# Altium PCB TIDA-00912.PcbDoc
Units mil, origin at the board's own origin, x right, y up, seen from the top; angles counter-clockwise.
Board outline 2371.35 x 1639 mil, 4 copper layers (Top Layer, GND, PWR, Bottom Layer), stack 79.834 mil thick; 79 components, 34 nets, 162 pads, 39 vias.
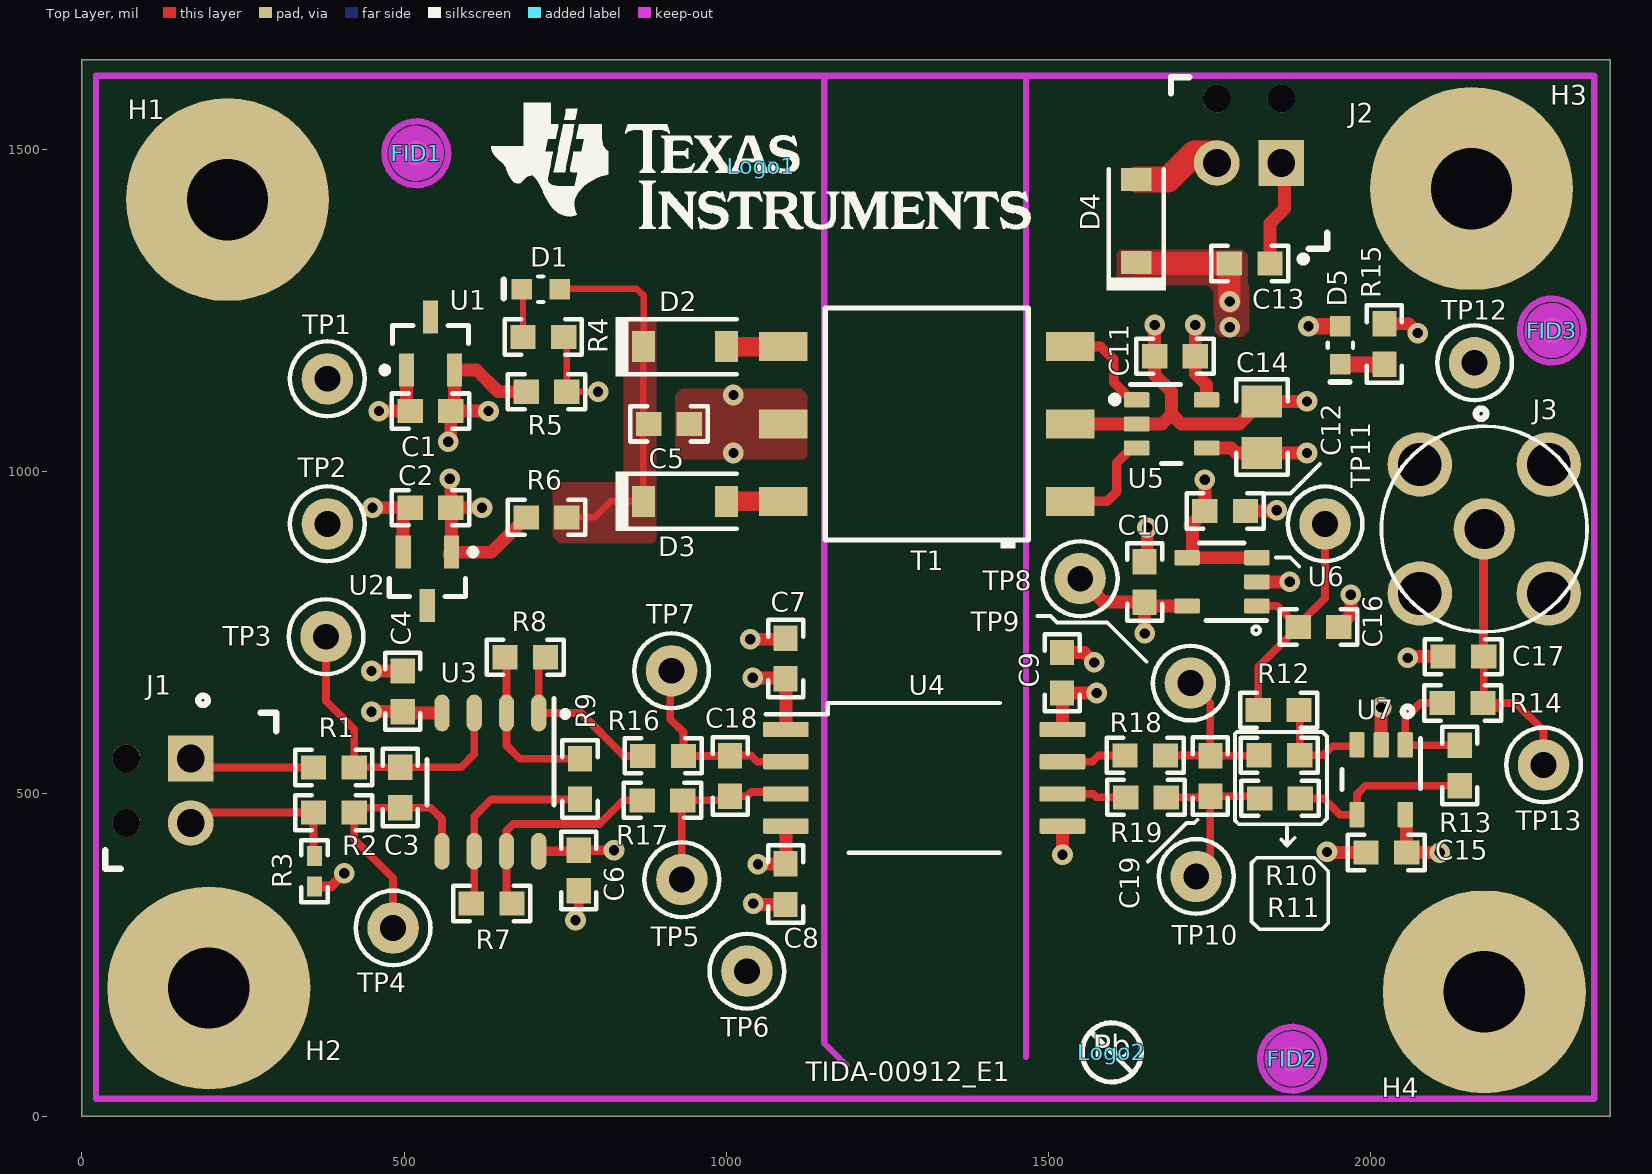
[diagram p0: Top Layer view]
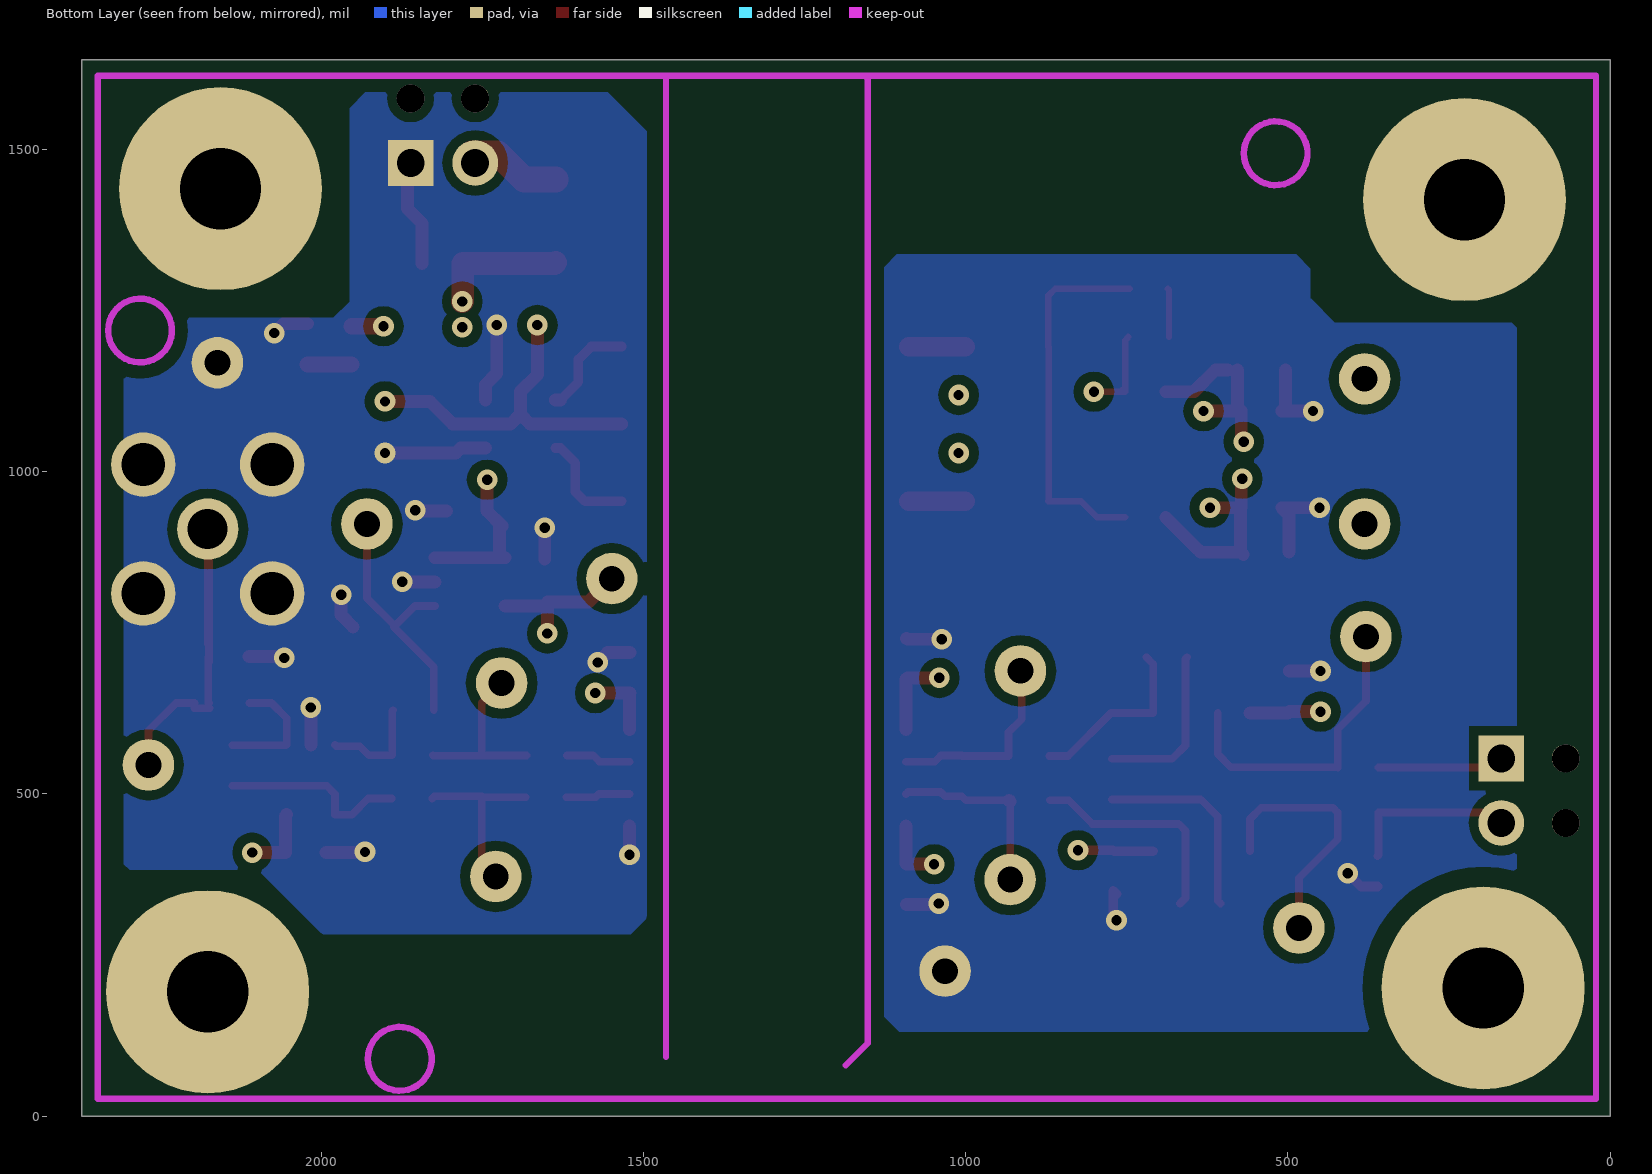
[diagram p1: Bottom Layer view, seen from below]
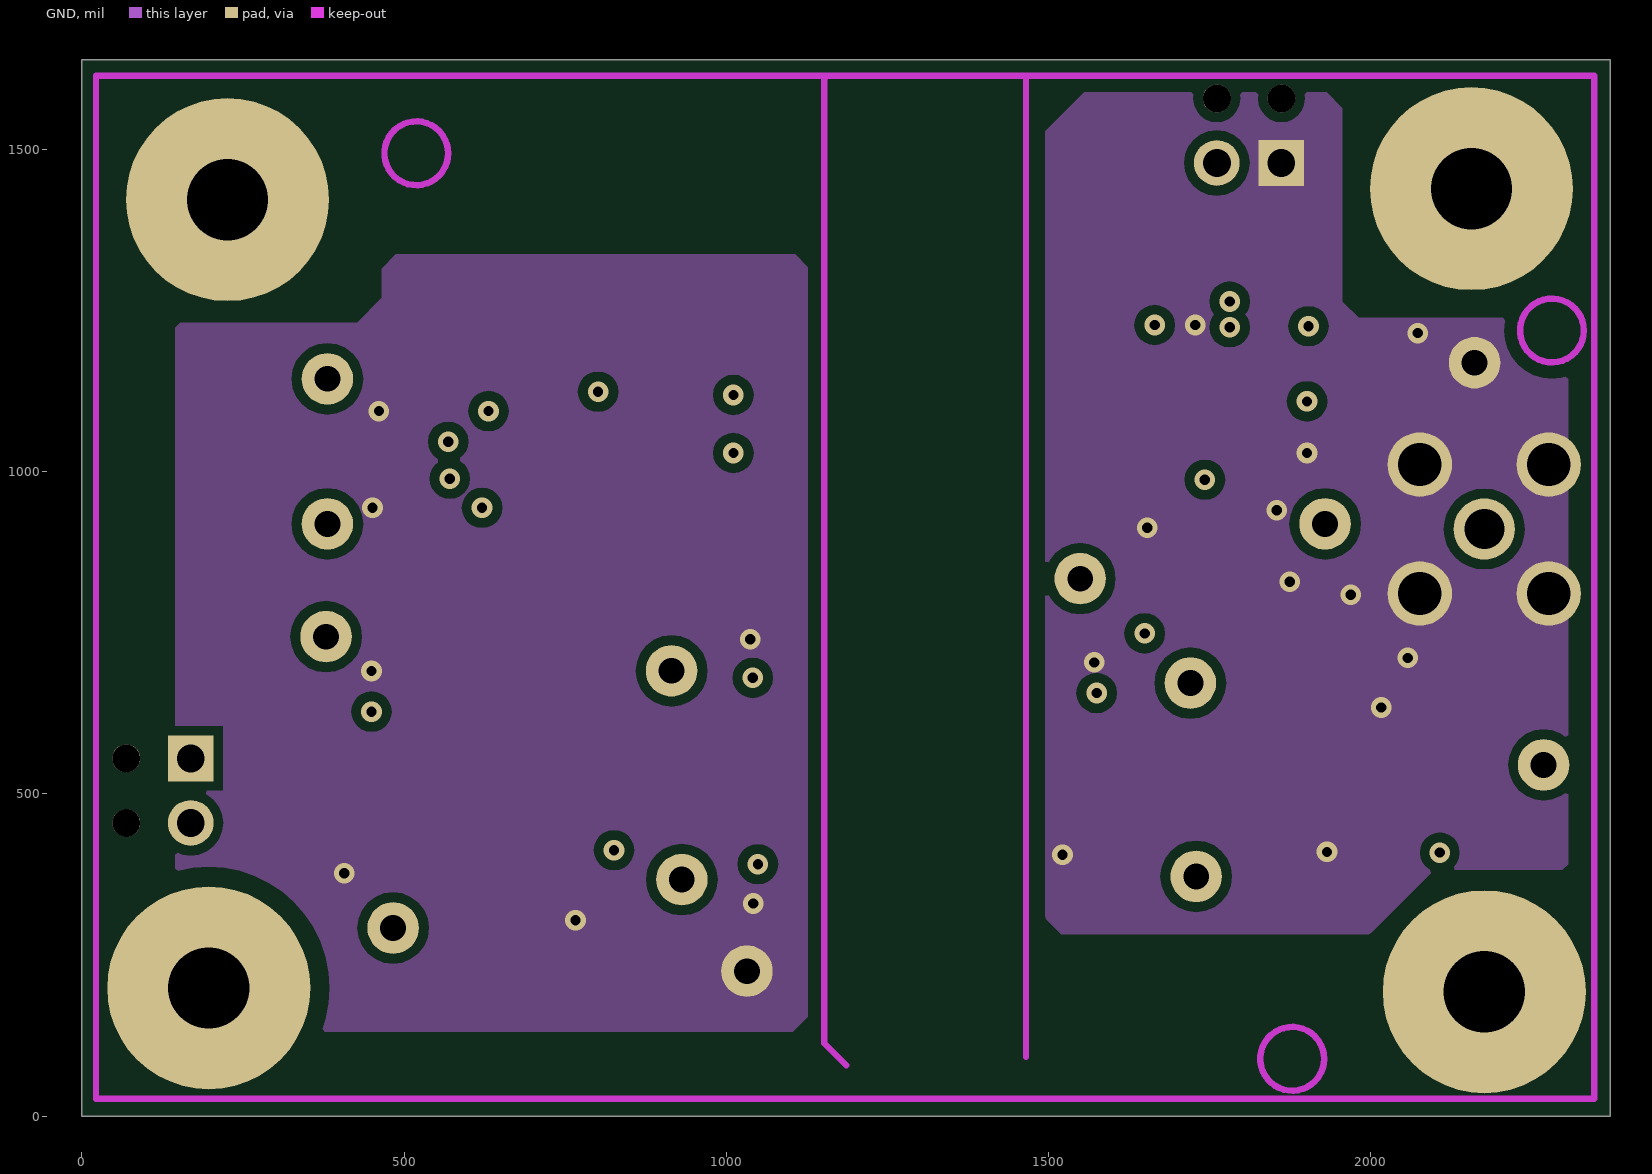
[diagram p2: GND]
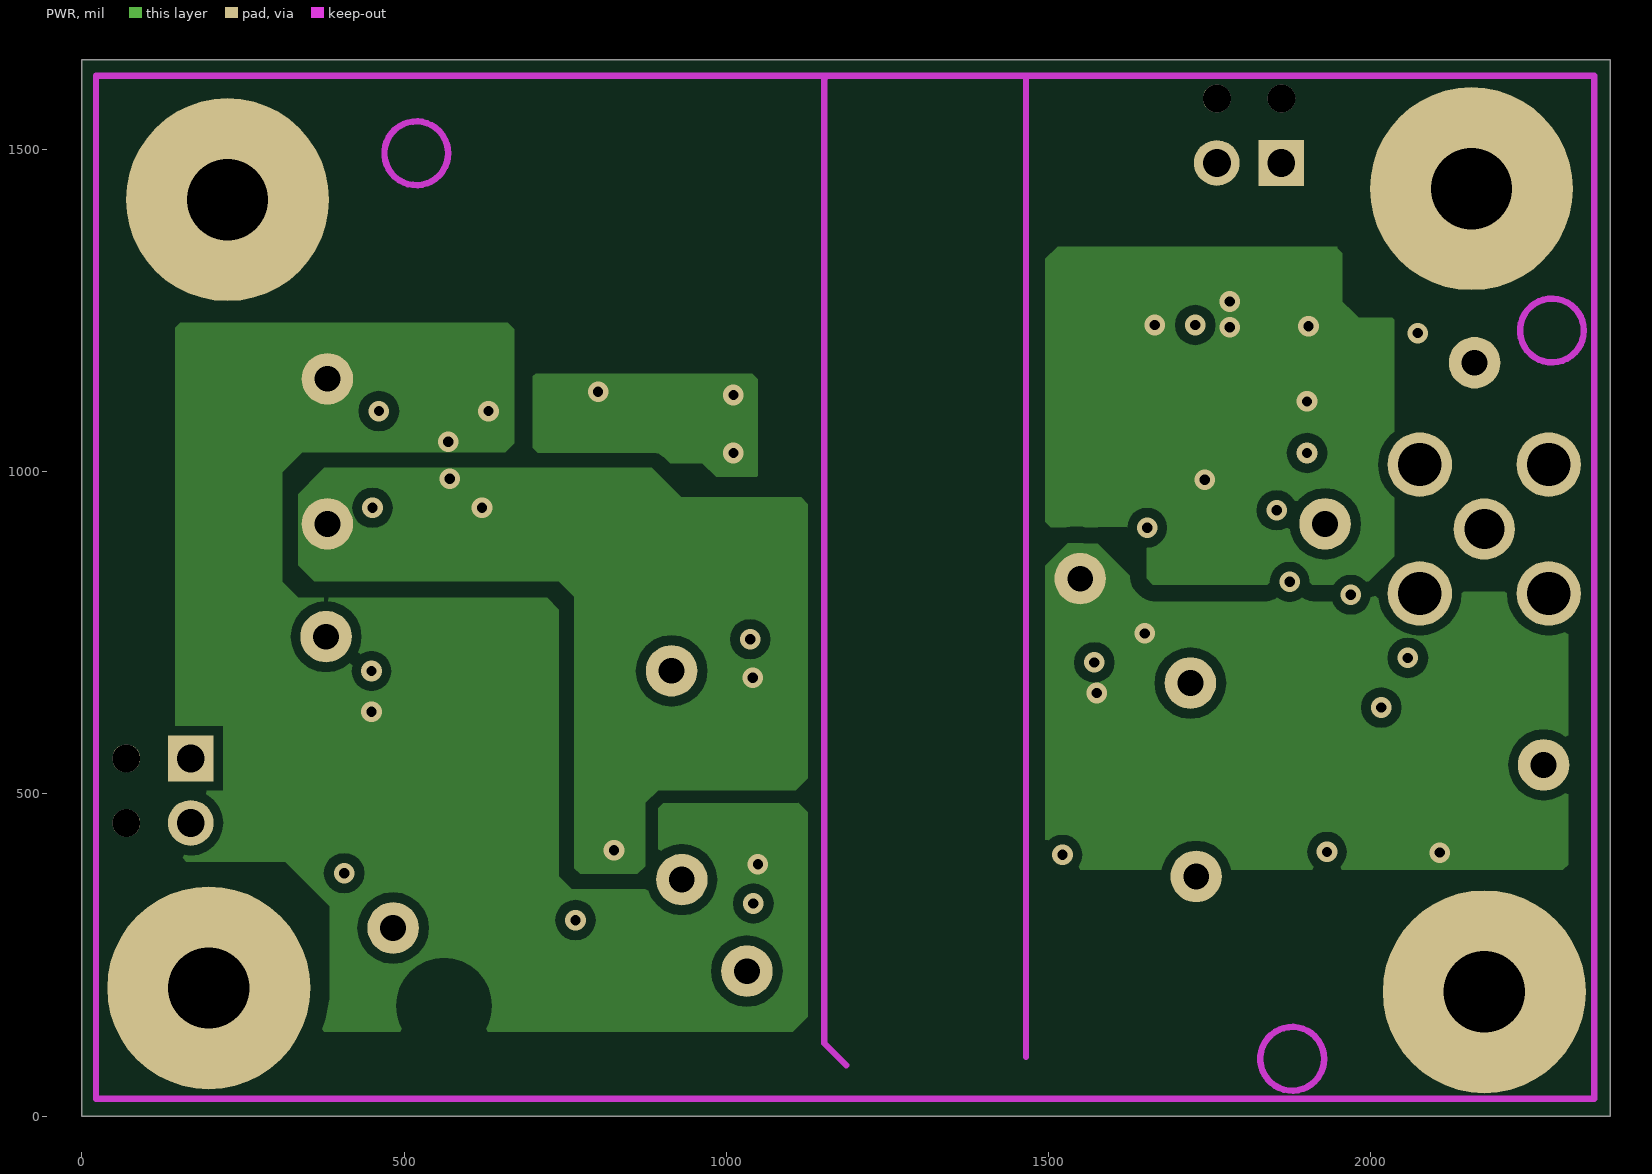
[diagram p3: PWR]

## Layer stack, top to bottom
Top Solder: solder mask 0.4, Solder Resist, Dk 3.5
Top Layer: signal copper 1.4
Dielectric1: core 59.2, FR-4, Dk 4.8
GND: signal copper 1.417
Dielectric 2: prepreg 5, Dk 4.2
PWR: signal copper 1.417
Dielectric 3: core 10, Dk 4.2
Bottom Layer: signal copper 1.4
Bottom Solder: solder mask 0.4, Solder Resist, Dk 3.5

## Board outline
0,0 0,1639 2371.36,1639 2371.36,0

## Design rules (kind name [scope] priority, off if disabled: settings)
AcuteAngle [All] p1: minimum=4.50000000000000E+0001 checktracksonly=FALSE
AssemblyTestPointUsage [All] p1: valid=2
Clearance Clearance_MTG_COPPER [InPadClass('MTG') vs InPolygon] p1: gap=30
Clearance Clearance_Boardedge_poly [OnCopper and InPolygon vs IsKeepOut] p2: gap=20
Clearance "Shape to Shape" [InPolygon vs InPolygon] p3: gap=20
Clearance "shape to all" [InPolygon] p4: gap=15
Clearance Clearance_u1 [IsPad vs IsPad] p5: gap=7.87
Clearance "Clearance_via_thr pin" [IsVia vs IsThruPin] p6: gap=8
Clearance "SMD to Via" [IsSMTPin vs IsVia] p7: gap=8
Clearance [All] p8: gap=8
DiffPairsRouting DiffPair_DiffPairsRouting [InDifferentialPair ('kan')] p1: maxlimit=10 minlimit=10 mostfreqgap=10 toplayer_minwidth=15 toplayer_maxwidth=15 toplayer_prefwidth=15 midlayer1_minwidth=15 midlayer1_maxwidth=15 midlayer1_prefwidth=15 midlayer2_minwidth=15 midlayer2_maxwidth=15 midlayer2_prefwidth=15 bottomlayer_minwidth=15 bottomlayer_maxwidth=15 bottomlayer_prefwidth=15 maxuncoupledlength=500
DiffPairsRouting DiffPair_DiffPairsRouting_1 [InDifferentialPair ('kan')] p2: maxlimit=10 minlimit=10 mostfreqgap=10 toplayer_minwidth=15 toplayer_maxwidth=15 toplayer_prefwidth=15 midlayer1_minwidth=15 midlayer1_maxwidth=15 midlayer1_prefwidth=15 midlayer2_minwidth=15 midlayer2_maxwidth=15 midlayer2_prefwidth=15 bottomlayer_minwidth=15 bottomlayer_maxwidth=15 bottomlayer_prefwidth=15 maxuncoupledlength=500
DiffPairsRouting [All] p3: maxlimit=100 minlimit=10 mostfreqgap=10 toplayer_minwidth=15 toplayer_maxwidth=15 toplayer_prefwidth=15 midlayer1_minwidth=15 midlayer1_maxwidth=15 midlayer1_prefwidth=15 midlayer2_minwidth=15 midlayer2_maxwidth=15 midlayer2_prefwidth=15 bottomlayer_minwidth=15 bottomlayer_maxwidth=15 bottomlayer_prefwidth=15 maxuncoupledlength=1000
FabricationTestPointUsage TestPointUsage [All] p1: valid=2 allowmultiple=FALSE
FabricationTestpoint Testpoint [All] p1: side=3 testpointundercomponent=TRUE minsize=40 maxsize=100 preferedsize=60 minholesize=0 maxholesize=40 preferedholesize=32 testpointgrid=1 allowsidetop=TRUE allowsidebottom=TRUE usegrid=TRUE gridtolerance=0.01
FanoutControl Fanout_LCC [IsLCC] p1: bgadir=Out bgaviamode=Centered fanoutstyle=Auto fanoutdirection=Alternating viagrid=1 // Fanout_LCC (Default Rule)
FanoutControl Fanout_BGA [IsBGA] p2: bgadir=Out bgaviamode=Centered fanoutstyle=Auto fanoutdirection=Alternating viagrid=1 // Fanout_BGA (Default Rule)
FanoutControl Fanout_Default [All] p4: bgadir=Out bgaviamode=Centered fanoutstyle=Auto fanoutdirection=Alternating viagrid=1 // Fanout_Default (Default Rule)
FanoutControl Fanout_Small [(CompPinCount < 5)] p5: bgadir=Out bgaviamode=Centered fanoutstyle=Auto fanoutdirection=OutThenIn viagrid=1 // Fanout_Small (Default Rule)
HoleSize [All] p1: absolutevalues=TRUE maxlimit=251 minlimit=7 maxpercent=80.000 minpercent=20.000
MatchedLengths DiffPair_MatchedLengths [InDifferentialPair ('kan')] p1: tolerance=1000 checknetsindiffpair=TRUE checkdiffpairvsdiffpair=TRUE checkothers=TRUE
MatchedLengths DiffPair_MatchedLengths_1 [InDifferentialPair ('kan')] p2: tolerance=1000 checknetsindiffpair=TRUE checkdiffpairvsdiffpair=TRUE checkothers=TRUE
MinimumAnnularRing [All] p1: minimumring=5
MinimumAnnularRing MinimumAnnularRing_ThermalPadVias [IsVia and InAnyComponent] p2: minimumring=5.91
MinimumSolderMaskSliver MinimumSolderMaskSliver_Logo [InComponentClass('Logo') vs InComponentClass('Logo')] p1: minsoldermaskwidth=0.7
MinimumSolderMaskSliver [All] p2: minsoldermaskwidth=3.94
PlaneClearance [All] p1: clearance=15
PlaneConnect [All] p1: planeconnectstyle=Direct reliefexpansion=10 reliefentries=4 reliefconductorwidth=10 reliefairgap=10
PolygonConnect [All] p1: connectstyle=Direct reliefconductorwidth=10 reliefentries=4 polygonreliefangle="90 Angle" airgapwidth=10
RoutingVias RoutingVias_power [InNetClass('POWER')] p1: holewidth=16 width=32 viastyle="Through Hole" minholewidth=7.87 minwidth=19.68 maxholewidth=16 maxwidth=32
RoutingVias ThermalPadVias [IsVia and InAnyComponent] p2: holewidth=8 width=20 viastyle="Through Hole" minholewidth=7.87 minwidth=19 maxholewidth=12 maxwidth=24
RoutingVias [All] p3: holewidth=12 width=24 viastyle="Through Hole" minholewidth=12 minwidth=24 maxholewidth=16 maxwidth=32
SMDToCorner [All] p1: distance=30000
SilkToSilkClearance [All] p1: silktosilkclearance=5
SilkToSolderMaskClearance SilkscreenOverComponentPads [IsPad] p1: minsilkscreentomaskgap=5 clearancetoexposedcopper=TRUE
SolderMaskExpansion [All] p1: expansion=3
UnpouredPolygon [All] p1: allowunpoured=FALSE
Width Width_power [InNetClass('pwr')] p1: maxlimit=200 minlimit=8 preferedwidth=20
Width [All] p2: maxlimit=100 minlimit=10 preferedwidth=20 checkconnectedcopper=TRUE
15 further rules are at their usual default settings.

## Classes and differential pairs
pad class MTG: H1-1 H2-1 H3-1
component class TIDA_00912_Schematic: C1 C2 C3 C4 C5 C6 C7 C8 C9 C10 C11 C12 C13 C14 C15 C16 C17 C18 C19 D1 D2 D3 D4 D5 J1 J2 J3 R1 R2 R3 R4 R5 R6 R7 R8 R9 R10 R11 R12 R13 R14 R15 R16 R17 R18 R19 T1 TP1 TP2 TP3 TP4 TP5 TP6 TP7 TP8 TP9 TP10 TP11 TP12 TP13 U1 U2 U3 U4 U5 U6 U7
component class AssemblyNote: ZZ1 ZZ2 ZZ3
component class FiducialMark: FID1 FID2 FID3
component class Logo: Logo1
component class "Mounting Holes": H1 H2 H3 H4
component class TIDA_00912_TID_Hardware: !PCB FID1 FID2 FID3 H1 H2 H3 H4 Logo1 Logo2 ZZ1 ZZ2 ZZ3

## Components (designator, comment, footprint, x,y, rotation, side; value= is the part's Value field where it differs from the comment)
C1 "C1608X7R1E105K080AB" 0603 541,1094 r0 top (schematic designator C21)
C2 "C1608X7R1E105K080AB" 0603 541,944 r180 top (schematic designator C22)
C3 "GRM188R71E224KA88D" 0603 494,510 r270 top (schematic designator C17)
C4 "C0603C104J3RAC" 0603 498,659.2 r270 top (schematic designator C9)
C5 "GRM188R6YA106MA73" 0603 911,1074 r0 top (schematic designator C20)
C6 "C0603C104J3RAC" 0603 771,381.2 r270 top
C7 "C0603C104J3RAC" 0603 1092,710 r90 top
C8 "C0603C104J3RAC" 0603 1092,360 r270 top (schematic designator C12)
C9 "C0603C104J3RAC" 0603 1521,688 r270 top (schematic designator C8)
C10 "C0603C104J3RAC" 0603 1649,829 r90 top (schematic designator C14)
C11 "C0603C104J3RAC" 0603 1696,1179 r0 top (schematic designator C1)
C12 "C0603C104J3RAC" 0603 1774,939 r180 top (schematic designator C2)
C13 "C1608X5R1E106M080AC" 0603 1812,1323 r0 top (schematic designator C3)
C14 "C2012X5R1E106K125AB" 0805_HV 1831,1069 r270 top (schematic designator C4)
C15 "C0603C104J3RAC" 0603 2024,409 r0 top (schematic designator C10)
C16 "C0603C104J3RAC" 0603 1919,759 r0 top (schematic designator C15)
C17 "C0603C224J3RAC7867" 0603 2143.5,713 r180 top (schematic designator C19)
C18 "C1608C0G1H331J" 0603 1006,528 r270 top
C19 "C1608C0G1H331J" 0603 1751,527.7 r270 top
D1 "LG L29K-G2J1-24-Z" "LG L29K_GREEN" 712,1283 r180 top (schematic designator D5)
D2 "MBR0540T1G" SOD-123 936,1194 r0 top
D3 "MBR0540T1G" SOD-123 936,954 r0 top (schematic designator D1)
D4 "MBR0520LT1G" SOD-123 1636,1389 r90 top (schematic designator D7)
D5 "LG L29K-G2J1-24-Z" "LG L29K_GREEN" 1952.76,1196.09 r270 top (schematic designator D6)
FID1 "Fiducial" Fiducial10-20 519,1494 r90 top
FID2 "Fiducial" Fiducial10-20 1878,89 r90 top
FID3 "Fiducial" Fiducial10-20 2281,1219 r90 top
H1 "NY PMS 440 0025 PH" "NY PMS 440 0025 PH" 226,1422 r0 top
H2 "NY PMS 440 0025 PH" "NY PMS 440 0025 PH" 197,199 r0 top
H3 "NY PMS 440 0025 PH" "NY PMS 440 0025 PH" 2156,1439 r0 top
H4 "NY PMS 440 0025 PH" "NY PMS 440 0025 PH" 2176,193 r90 top
J1 "1725656" CONN_1725656 169,505 r270 top (schematic designator J2)
J2 "1725656" CONN_1725656 1811,1479 r180 top (schematic designator J1)
J3 "142-0701-201" Johnson_142-0701-20x 2176,911 r270 top (schematic designator J4)
Logo1 "Texas Instruments" TI_Stacked_Overlay_Small 1054,1474 r0 top
Logo2 "Pb-Free Symbol" Pb-Free_Overlay_Small 1598,99 r0 top
R1 "CRCW060318R0JNEA" 0603 391,541 r0 top
R2 "CRCW060318R0JNEA" 0603 391,471 r0 top (schematic designator R10)
R3 "CRCW04020000Z0ED" 0402 361,380 r90 top (schematic designator R13)
R4 "ERJ-3EKF1001V" 0603 716,1209 r180 top (schematic designator R12)
R5 "CRCW0603576RFKEA" 0603 721,1124 r180 top (schematic designator R15)
R6 "CRCW0603576RFKEA" 0603 721,929 r0 top (schematic designator R11)
R7 "CRCW06036K34FKEA" 0603 636,330 r0 top (schematic designator R8)
R8 "RG1608P-512-B-T5" 0603 688,712 r0 top (schematic designator R3)
R9 "RT0603BRD071K27L" 0603 773,523 r90 top (schematic designator R5)
R10 "CRCW060320K0FKEA" 0603 1858,560 r0 top (schematic designator R7)
R11 "CRCW060320K0FKEA" 0603 1859,493 r0 top (schematic designator R6)
R12 "RC0603FR-0715KL" 0603 1857,630 r0 top (schematic designator R9)
R13 "RC0603FR-0715KL" 0603 2138,544 r90 top (schematic designator R4)
R14 "CRCW060336R0JNEA" 0603 2142.5,641 r0 top (schematic designator R2)
R15 "ERJ-3EKF1001V" 0603 2021,1198 r270 top (schematic designator R14)
R16 "RT0603BRD0712RL" 0603 902,559 r0 top
R17 "RT0603BRD0712RL" 0603 901,490 r0 top
R18 "RT0603BRD0712RL" 0603 1650,559.7 r0 top
R19 "RT0603BRD0712RL" 0603 1651,494.7 r0 top
T1 "750342879" Wurth_750342879 1311,1074 r180 top
TP1 "5000" Keystone5000 381,1144 r180 top (schematic designator TP9)
TP2 "5000" Keystone5000 381,919 r0 top (schematic designator TP8)
TP3 "5000" Keystone5000 379,744 r0 top (schematic designator TP1)
TP4 "5000" Keystone5000 483,292 r0 top (schematic designator TP7)
TP5 "5000" Keystone5000 931,367 r180 top
TP6 "5000" Keystone5000 1032,225 r180 top (schematic designator TP13)
TP7 "5000" Keystone5000 915,691 r180 top (schematic designator TP3)
TP8 "5000" Keystone5000 1549,834 r0 top (schematic designator TP10)
TP9 "5000" Keystone5000 1720,672 r180 top (schematic designator TP4)
TP10 "5000" Keystone5000 1729,372 r180 top (schematic designator TP6)
TP11 "5000" Keystone5000 1929,919 r180 top
TP12 "5000" Keystone5000 2161,1169 r180 top
TP13 "5000" Keystone5000 2268,545 r0 top (schematic designator TP2)
U1 "LM4040BIM3-2.5" MF03A_N 541,1199 r90 top (schematic designator U7)
U2 "LM4040BIM3-2.5" MF03A_N 536,834 r270 top (schematic designator U5)
U3 "OPA2376AID" D0008A_N 633.91,518.24 r270 top (schematic designator U2)
U4 "AMC1301DWVR" DWV0008A 1307,525 r0 top (schematic designator U3)
U5 "SN6501DBVR" DBV0005A_N 1691,1074 r0 top (schematic designator U1)
U6 "REF2033AIDDCR" DDC0005A_N 1769,829 r180 top
U7 "OPA376AIDBVR" DBV0005A_N 2016,522 r270 top (schematic designator U4)
ZZ1 "These assemblies are ESD sensitive, ESD precautions shall be observed." AssemblyNote 97,3153 r0 top
ZZ2 "These assemblies must comply with workmanship standards IPC-A-610 Class 2, unless otherwise specified." AssemblyNote 96,3024 r0 top
ZZ3 "These assemblies must be clean and free from flux and all contaminants. Use of no clean flux is not acceptable." AssemblyNote 96,3099 r0 top

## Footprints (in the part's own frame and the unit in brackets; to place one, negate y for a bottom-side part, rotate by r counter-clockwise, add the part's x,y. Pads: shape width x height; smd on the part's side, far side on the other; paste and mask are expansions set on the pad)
0402 [mm] "0402 from SM-752 data"
  rect 0.8x0.6 smd: 1(-0.6,0) 2(0.6,0)
  silkscreen extent -1.22,-0.52 1.22,0.52, body extent -0.55,-0.3 0.55,0.3, height 0.6
0603 [mm] "0603 from SM-752 data"
  rect 1x0.95 smd: 1(-0.8,0) 2(0.8,0)
  silkscreen extent -1.52,-0.69 1.52,0.69, body extent -0.87,-0.47 0.87,0.47, height 0.85
0805_HV [mil] "0805 with 30mil clearance between pads"
  rect 50x63 smd: 1(-40,0) 2(40,0)
  silkscreen extent -74,-40 74,40, body extent -43,-29 43,29, height 57
AssemblyNote [mil] "Assembly Note"
CONN_1725656 [mm] "Phoenix Contact"
  rect 1.8x1.8 hole 1.1: 1(-1.27,0)
  round 1.8 hole 1.1: 2(1.27,0)
  round 1.1 hole 1.1 unplated mask+0.254: MH1(-1.275,-2.54) MH2(1.27,-2.54)
  silkscreen extent -3.08,-3.37 3.08,3.37, body extent -2.77,-3.1 2.77,3.1, height 8.52
D0008A_N [mm] "SOIC, 8-Leads, Body 4.9x3.9mm, Pitch 1.27mm, IPC Medium Density"
  oval 1.45x0.6 smd: 1(-2.725,1.905) 2(-2.725,0.635) 3(-2.725,-0.635) 4(-2.725,-1.905) 5(2.725,-1.905) 6(2.725,-0.635) 7(2.725,0.635) 8(2.725,1.905)
  silkscreen extent -3.3,-2.5 0.9,2.5, body extent -3,-2.45 3,2.45, height 1.63
DBV0005A_N [mm] "SOT23, 5-Leads, Body 2.9x1.6mm, Pitch 0.95mm, Lead Span 2.8mm, IPC Medium Density"
  rrect17% 1x0.6 smd: 1(-1.375,0.95) 2(-1.375,0) 3(-1.375,-0.95) 4(1.375,-0.95) 5(1.375,0.95)
  silkscreen extent -1.63,-1.55 0.38,1.55, body extent -1.42,-1.46 1.42,1.46, height 1.09
DDC0005A_N [mm]
  rrect17% 1x0.6 smd: 1(-1.375,0.95) 2(-1.375,0) 3(-1.375,-0.95) 4(1.375,-0.95) 5(1.375,0.95)
  silkscreen extent -1.75,-1.52 0.88,1.53, body extent -1.41,-1.45 1.41,1.45, height 1.1
DWV0008A [mm] "SOIC, 8-Leads, Body 5.95x7.6mm (max), Pitch 1.27mm"
  rrect17% 1.8x0.6 smd: 1(-5.45,1.905) 2(-5.45,0.635) 3(-5.45,-0.635) 4(-5.45,-1.905) 5(5.45,-1.905) 6(5.45,-0.635) 7(5.45,0.635) 8(5.45,1.905)
  silkscreen extent -6.25,-2.95 2.98,2.95, body extent -5.77,-2.92 5.77,2.93, height 2.67
Fiducial10-20 [mm]
  round 1 smd mask+0.5: 1(0,0)
  Top Layer keep-out circle w1.178: c0,0 r0.5
Johnson_142-0701-20x [mil] "Johnson Components recommended land pattern"
  round 95 hole 62: 1(0,0)
  round 100 hole 67: 2(100,100) 3(100,-100) 4(-100,-100) 5(-100,100)
  body extent -156,-156 156,156, height 375
Keystone5000 [mil] "For Keystone 500x miniature loop terminals"
  round 80 hole 40: 1(0,0)
  silkscreen extent -58,-58 58,58, body extent -49,-49 49,49, height 182
"LG L29K_GREEN" [mm] "OSRAM"
  rect 0.8x0.8 smd paste-0.4: 1(-0.75,0) 2(0.75,0)
  silkscreen extent -0.1,-0.5 1.45,0.5, body extent -0.9,-0.45 0.9,0.45, height 0.67
MF03A_N [mm] "SOT23, 3-Leads, Body 2.9x1.3mm, Pitch 0.95mm, Lead Span 2.4mm, IPC Medium Density"
  rect 1.3x0.6 smd: 1(-1.05,0.95) 2(-1.05,-0.95) 3(1.05,0)
  silkscreen extent -1.17,-1.5 0.7,1.92, body extent -0.7,-1.5 0.7,1.5, height 1.12
"NY PMS 440 0025 PH" [mm] "4-40 nylon screw and mounting hole"
  round 8 hole 3.2 unplated: 1(0,0)
  body extent -3.3,-3.3 3.3,3.3, height 2.69
Pb-Free_Overlay_Small [mil]
  silkscreen extent -46,-46 46,46
SOD-123 [mm] "On Semi recommended land pattern"
  rect 0.915x1.22 smd: 1(-1.637,0) 2(1.637,0)
  silkscreen extent -2.74,-1.17 2.03,1.17, body extent -1.93,-0.9 1.93,0.9, height 1.35
TI_Stacked_Overlay_Small [mil]
  silkscreen extent -418,-98 418,98
Wurth_750342879 [mm] "SMD, 6-Leads, Body 9.14x8mm, Pitch 3.05mm"
  rect 1.9x1.14 smd: 1(-5.655,3.05) 2(-5.655,0) 3(-5.655,-3.05) 4(5.655,-3.05) 5(5.655,0) 6(5.655,3.05)
  silkscreen extent -4,-4.57 4,4.9, body extent -6.35,-4.57 6.35,4.57, height 7.83

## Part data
C1 C2: "CAP, CERM, 1 µF, 25 V, +/- 10%, X7R, 0603"
C3: "CAP, CERM, 0.22 µF, 25 V, +/- 10%, X7R, 0603"
C4 C6 C7 C8 C9 C10 C11 C12 C15 C16: "CAP, CERM, 0.1 µF, 25 V, +/- 5%, X7R, 0603"
C5: "CAP, CERM, 10 µF, 35 V, +/- 20%, X5R, 0603"
C13: "CAP, CERM, 10 µF, 25 V, +/- 20%, X5R, 0603"
C14: "CAP, CERM, 10 µF, 25 V, +/- 10%, X5R, 0805"
C17: "CAP, CERM, 0.22 µF, 25 V, +/- 5%, X7R, 0603"
C18 C19: "CAP, CERM, 330 pF, 50 V, +/- 5%, C0G/NP0, 0603"
D1 D5: "LED, Green, SMD"
D2 D3: "Diode, Schottky, 40 V, 0.5 A, SOD-123"
D4: "Diode, Schottky, 20 V, 0.5 A, SOD-123"
FID1 FID2 FID3: "Fiducial mark.  There is nothing to buy or mount."
H1 H2 H3 H4: "Machine Screw, Round, #4-40 x 1/4, Nylon, Philips panhead"
J1 J2: "Terminal Block, 100mil, 2x1, 6A, 63V, TH"
J3: "Connector, TH, SMA"
Logo1: library part TI_Logo, "Texas Instrument Corporate Signature"
Logo2: library part Pb-Free
R1 R2: "RES, 18, 5%, 0.1 W, 0603"
R3: "RES, 0, 5%, 0.063 W, 0402"
R4 R15: "RES, 1.00 k, 1%, 0.1 W, 0603"
R5 R6: "RES, 576, 1%, 0.1 W, 0603"
R7: "RES, 6.34 k, 1%, 0.1 W, 0603"
R8: "RES, 5.10 k, 0.1%, 0.1 W, 0603"
R9: "RES, 1.27 k, 0.1%, 0.1 W, 0603"
R10 R11: "RES, 20.0 k, 1%, 0.1 W, 0603"
R12 R13: "RES, 15.0 k, 1%, 0.1 W, 0603"
R14: "RES, 36, 5%, 0.1 W, 0603"
R16 R17 R18 R19: "RES, 12.0, 0.1%, 0.1 W, 0603"
T1: "Transformer, 50 uH, SMT"
TP1 TP2 TP3 TP4 TP5 TP6 TP7 TP8 TP9 TP10 TP11 TP12 TP13: "Test Point, Miniature, Red, TH"
U1 U2: "Precision Micropower Shunt Voltage Reference, 3-pin SOT-23"
U3: "Precision, Low Noise, Low Quiescent Current Operational Amplifier, 2 to 5.5 V, -40 to 125 degC, 8-pin SOIC (D0008A), Green (RoHS & no Sb/Br)"
U4: "200 kHz, Fully-Differential Isolation Amplifier, DWV0008A"
U5: "Transformer Driver for Isolated Power Supplies, DBV0005A"
U6: "Low-Drift, Low-Power, Dual-Output, VREF and VREF / 2 Voltage References, DDC0005A"
U7: "Precision, Low Noise, Low Iq Operational Amplifier, 2.2 to 5.5 V, -40 to 125 degC, 5-pin SOT23 (DBV0005A), Green (RoHS & no Sb/Br)"
ZZ1 ZZ2 ZZ3: library part AssemblyNote

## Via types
v1: diameter 32, hole 16, Top Layer to Bottom Layer, tented both sides, 39 vias

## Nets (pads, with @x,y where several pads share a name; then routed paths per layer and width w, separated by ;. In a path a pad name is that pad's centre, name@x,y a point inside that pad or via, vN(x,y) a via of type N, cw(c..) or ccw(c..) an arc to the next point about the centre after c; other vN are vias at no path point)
GND1: C1.1 C2.2 C4.1 C6.2 C7.2 C8.2 R3.1 TP6.1 U1.1 U2.2 | length 512.3
  Top Layer w15: R3.1 386.38,356.38 v1(407,377) ; v1(766,304.2) 771,309.2 C6.2 C6.2@766,344.7
  Top Layer w20: v1(449.5,690.7) C4.1 ; v1(451,944) C2.2 498.6,933.1 U2.2 ; v1(461,1094) C1.1 503.6,1099.91 U1.1 ; v1(1037,740) 1090.5,740 C7.2 ; v1(1042,330) 1043.5,328.51 C8.2
  Bottom Layer w12: v1@452,696.19 v1@453.5,694.7
GND2: C9.1 C10.2 C11.2 C12.1 C13.2 C14.2 C15.1 C16.2 C17.2 J2.1 J3.2 J3.3 J3.4 J3.5 R15.1 TP12.1 U4.5 U5.4 U5.5 U6.2 U7.2 | length 1008.7
  Top Layer w20: C9.1 1555.5,719.5 v1(1571,704) ; v1(1521.57,405.43) U4.5 ; C10.2@1653,864.5 v1(1653,913) ; v1(1727.5,1227.51) C11.2 1727.5,1152.51 1745.13,1134.87 U5.5 ; U5.4 1783.4,1036.6 1791,1029 C14.2 v1(1901,1029) ; C12.1 1853,939 v1(1854,940) ; U6.2 v1(1874,829) ; C13.2 1843.5,1385.5 1866,1408 J2.1@1866,1494 ; v1(1932,410) 1932,407.56 1933.44,409 C15.1 ; C16.2 1969,777.51 v1(1969,809) ; U7.2 v1(2016,634) ; R15.1 2058.5,1229.5 v1(2073,1215) ; v1(2057.5,711) 2059.5,713 C17.2
  Bottom Layer w12: v1(1653,913) v1@1654.5,914.5 ; v1(1727.5,1227.51) v1@1728.99,1229
NetC3_1: C3.1 R1.2 TP3.1 U3.3 | length 479.7
  Top Layer w12: TP3.1 379,644 422.5,600.5 R1.2 422.99,541.5 C3.1 588.5,541.5 608.91,561.91 U3.3
NetC3_2: C3.2 R2.2 TP4.1 U3.5 | length 400.9
  Top Layer w12: TP4.1 483,369 422.5,429.5 R2.2 430,478.5 C3.2 541.5,478.5 558.91,461.09 U3.5
NetC5_1: C5.1 D1.1 D2.1 D3.1 R6.2 | length 579.7
  Top Layer w10: D1.1@745.53,1284 861,1284 871.53,1273.47 D2.1 871,1193.47 871,1074 871,954.53 D3.1 821,954 796,929 R6.2
NetC5_2: C5.2 R4.1 R5.1 T1.5 | length 140.5
  Top Layer w10: R4.1 752.5,1204 R5.1 ; R5.1@756,1127.5 R5.1 ; v1(801,1124) R5.1
  other v1: 1011,1029 1011,1119
NetC17_1: C17.1 J3.1 R14.2 TP13.1 | length 623.1
  Top Layer w12: R14.2@2173,633 2196.68,633 ; R14.2 2175,642 C17.1 ; C17.1@2174,705 2174,909 J3.1 2176,733 ; 2196.68,641 2225,641 2268,598 TP13.1
NetC18_1: C18.1 R16.2 TP7.1 U4.2 | length 304.4
  Top Layer w12: TP7.1@913,689 913,616 933.5,595.5 R16.2 1005.5,559 C18.1 1038.5,559.5 1048,550 U4.2
  Top Layer w20: TP7.1@913,689 TP7.1
NetC18_2: C18.2 R17.2 TP5.1 U4.3 | length 290.2
  Top Layer w12: TP5.1 R17.2@931,488.5 ; R17.2 999.5,490 C18.2 1032.5,496.5 1039,503 1089.43,503 U4.3
  Top Layer w20: R17.2@931,488.5 R17.2
NetD1_2: D1.2 R4.2 | length 75.8
  Top Layer w10: R4.2 684.5,1282.03 D1.2@686.47,1284
NetD2_2: D2.2 T1.4 | length 87.9
  Top Layer w12: T1.4@1088.28,1194 T1.4
  Top Layer w30: D2.2 T1.4@1088.28,1194
NetD3_2: D3.2 T1.6 | length 87.9
  Top Layer w12: T1.6@1088.28,954 T1.6
  Top Layer w30: D3.2 T1.6@1088.28,954
NetD4_2: D4.2 J2.2 | length 146.8
  Top Layer w40: D4.2 1685.47,1453.47 1726,1494 J2.2@1766,1494
NetD5_2: D5.2 R15.2 | length 68.3
  Top Layer w25: D5.2 2020.95,1166.56 R15.2
NetJ1_1: J1.1 R1.1 | length 196.3
  Top Layer w12: J1.1 183,541 R1.1
NetJ1_2: J1.2 R2.1 R3.2 | length 265.1
  Top Layer w12: J1.2 185,471 R2.1 359.5,405.12 R3.2
NetR7_1: R7.1 R9.1 U3.6 | length 311.8
  Top Layer w12: R7.1 608.91,334.41 U3.6 608.91,464.91 635.5,491.5 R9.1
NetR7_2: R7.2 R17.1 U3.7 | length 346.5
  Top Layer w12: R7.2 658.91,338.59 U3.7 658.91,442.74 669.68,453.5 803.5,453.5 840,490 R17.1
NetR8_1: R8.1 R9.2 U3.2 | length 260.5
  Top Layer w12: R8.1 658.91,709.6 U3.2 658.91,575.09 679.5,554.5 R9.2
NetR8_2: R8.2 R16.1 U3.1 | length 280
  Top Layer w12: R8.2 708.91,701.41 U3.1 774.47,625.53 841,559 R16.1
NetR10_2: R10.2 R12.2 U7.3 | length 166.2
  Top Layer w12: R12.2 1889.5,629 R10.2 1926,560 1940,574 1976.47,574 U7.3
NetR11_2: R11.2 R13.1 U7.4 | length 295
  Top Layer w12: R11.2 1927,493 1952.13,467.87 U7.4 1978.6,499.6 1991.5,512.5 R13.1
NetR13_2: R13.2 R14.1 U7.1 | length 193.5
  Top Layer w12: R14.1 2077,641 2053.4,617.4 U7.1 2054.04,575.5 R13.2
NetR18_1: R18.1 U4.7 | length 101
  Top Layer w12: U4.7 1568,550 1577.7,559.7 R18.1
NetR19_1: R19.1 U4.6 | length 100.1
  Top Layer w12: U4.6 1569,500 1574.3,494.7 R19.1
NetT1_1: T1.1 U5.3 | length 163.8
  Top Layer w15: T1.1 1590.92,953.92 1606,969 1606,1014 1628.6,1036.6 U5.3
NetT1_3: T1.3 U5.1 | length 158
  Top Layer w15: T1.3 1580.92,1194.08 1601,1174 1601,1139 U5.1@1628.6,1111.4
  Top Layer w20: U5.1@1628.6,1111.4 U5.1
P5V: C11.1 C12.2 C13.1 C14.1 D4.1 D5.1 T1.2 U5.2 U6.3 U6.4 | length 1042.7
  Top Layer w12: U6.4 U6.4@1719,870.54
  Top Layer w20: T1.2 U5.2 1676,1074 1691,1089 ; v1(1664.5,1227.51) C11.1 1664.5,1150.5 1691,1124 1691,1089 ; U6.4 U6.3 ; 1719,915.5 C12.2 v1(1742.5,987.51) ; U6.4@1723,874.54 1723,919.5 ; v1(1901,1109) C14.1 1796,1074 1706,1074 1691,1089
  Top Layer w25: v1(1903.24,1225.62) D5.1
  Top Layer w35: D4.1 1637.53,1323 C13.1 1780.5,1264.5 v1(1781,1264)
  Bottom Layer w12: v1(1664.5,1227.51) v1@1666,1229 ; v1@1746.5,991.51 v1@1748,993
  other v1: 1781,1224
V1.65: C16.1 R12.1 TP11.1 U6.1 | length 409.7
  Top Layer w12: U6.1 1854.91,791.6 C16.1 ; R12.1 1825.5,697 C16.1 ; TP11.1 1929,804 1887.5,762.5 C16.1
V3.3: C9.2 C10.1 C15.2 TP8.1 U4.8 U6.5 U7.5 | length 453.3
  Top Layer w20: U4.8 1521.57,655.94 C9.2 v1(1574.5,656.51) ; TP8.1 1585.5,797.5 C10.1 ; v1(1649,749) C10.1 ; U6.5 1654.91,791.6 C10.1 ; U7.5@2053.5,467.77 2055.5,465.77 C15.2 v1(2107,409)
VCC: C2.1 C6.1 C7.1 R6.1 TP2.1 U2.1 U3.8 U4.1 | length 552.7
  Top Layer w15: U3.8 769.26,410.96 C6.1 v1(825.7,412.7)
  Top Layer w20: TP2.1 TP2.1@383.4,916.6 ; U2.1@569.4,871.34 573.06,875 635.5,875 ; v1(571,989) 572.5,987.5 C2.1 ; U2.1 573.4,943.1 C2.1 ; v1(621,944) C2.1 ; 639.5,879 R6.1 ; v1(1041,680) 1090.5,680 C7.1 1092.43,678.07 U4.1
VEE: C1.2 C4.2 C8.1 R5.2 TP1.1 U1.2 U3.4 U4.4 | length 504.1
  Top Layer w20: TP1.1 TP1.1@383.6,1141.4 ; v1(449.5,627.7) C4.2 500.18,625.53 U3.4 ; v1(568.5,1046.5) 566,1049 572.5,1055.5 C1.2 ; U1.2 578.4,1099.91 C1.2 ; 593.21,1157.66 612.34,1157.66 646,1124 R5.2 ; v1(631,1094) C1.2 ; v1(1049,391) 1049.5,391.5 C8.1 1092.43,391.93 U4.4
  Bottom Layer w12: v1@452,633.2 v1@453.5,631.7
VINN: C19.2 R11.1 R19.2 TP10.1 | length 280.3
  Top Layer w12: R19.2 1749.5,494.7 C19.2 ; TP10.1 1751,394 C19.2 ; R11.1 1824.3,496.21 C19.2
VINP: C19.1 R10.1 R18.2 TP9.1 | length 271.2
  Top Layer w12: R18.2 1750.5,559.7 C19.1 ; TP9.1 1751,641 C19.1 ; R10.1 1825.7,559.2 C19.1
pads on no net: FID1.1 FID2.1 FID3.1 H1.1 H2.1 H3.1 H4.1 J1.MH1 J1.MH2 J2.MH1 J2.MH2 U1.3 U2.3

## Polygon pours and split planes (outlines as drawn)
GND2 on GND "Bottom Layer-No Net" (solid, remove dead copper, pour order 17): 1495,1528 1556,1589 1931,1589 1956,1564 1956,1264 1981,1239 2206,1239 2281,1239 2306,1214 2306,514 2306,391 2297,382 2098,382 1981,265 1981,164 1981,139 1956,114 1495,114
GND1 on GND "GND-No Net" (solid, remove dead copper, pour order 15): 145,1217 145,377 231,291 318,291 345,264 345,160 360,145 374,131 606,131 1103,131 1126.51,154.51 1126.51,1568.49 1106.49,1588.51 482.51,1588.51 464,1570 464,1268 427,1231 153,1231 145,1223
VEE on PWR "Top Layer-No Net" (solid, pour order 22): 671,1221 671,1044 657,1030 342,1030 311,999 311,829 336,804 722,804 740,786 740,372 760,352 874,352 889,367 889,478 901,490 1108,490 1124,474 1127,471 1127,402 1127,155 1103,131 436,131 371,131 385,182 385,325.35 339.35,371 315.35,395 232,395 162,395 145,412 145,750 145,1223 153,1231 661,1231 668,1224
VCC on PWR "Top Layer-No Net" (solid, pour order 20): 336,965 336,855 361,830 546.44,830 740,830 764,806 764,385 773,376 862,376 874,388 874,486 894,506 1108,506 1127,525 1127,949 1116,960 930,960 884,1006 376,1006 369,999
P5V on PWR "Top Layer-No Net" (solid, pour order 14): 1514,1349 1495,1330 1495,922 1503,914 1637,914 1652,899 1652,834.54 1661.79,824.74 1991.74,824.74 2036,869 2036,1236 2033,1239 2001,1239 1981,1239 1972.28,1247.72 1956,1264 1956,1339 1948,1347 1948,1349 1514,1349
V3.3 on PWR "Top Layer-No Net" (solid, pour order 18): 1566,889 1530,889 1495,854 1495,382 2298,382 2306,390 2306,751 2243,814 1651,814 1576,889
NetC5_2 on PWR "Top Layer-No Net" (solid, pour order 24): 1038,1152 704,1152 700,1148 700,1037 724,1013 963,1013 984,992 1047,992 1049,994 1049,1143 1040,1152
NetC5_1 on Top Layer "Top Layer-No Net" (solid, pour order 23): 891,1219 891,894 886,889 741,889 731,899 731,978.51 736,983.51 828.01,983.51 841,996.5 841,1233 848,1240 887.5,1240 891,1236.5
NetC5_2 on Top Layer "Top Layer-No Net" (solid, pour order 21): 921,1094 921,1024 926,1019 1121,1019 1131,1029 1131,1114 1116,1129 931,1129 921,1119
P5V on Top Layer "Top Layer-No Net" (solid, pour order 19): 1801,1344 1611,1344 1606,1339 1606,1294 1611,1289 1746,1289 1756,1279 1756,1219 1766,1209 1801,1209 1811,1219 1811,1334 1801,1344
GND2 on Bottom Layer "Bottom Layer-No Net" (solid, remove dead copper, pour order 16): 1495,1528 1556,1589 1931,1589 1956,1564 1956,1264 1981,1239 2206,1239 2281,1239 2306,1214 2306,514 2306,391 2297,382 2098,382 1981,265 1981,164 1981,139 1956,114 1495,114
GND1 on Bottom Layer "GND-No Net" (solid, remove dead copper, pour order 13): 145,1217 145,377 231,291 318,291 345,264 345,160 360,145 374,131 606,131 1103,131 1126.51,154.51 1126.51,1568.49 1106.49,1588.51 482.51,1588.51 464,1570 464,1268 427,1231 153,1231 145,1223

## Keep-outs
Keep-Out Layer:
  lines w10: 1156,1614 1152,1610 1152,913 1152,113 1186,79 ; 1465,92 1465,892 ; 1465,887 1465,1612 ; 22,27 22,1614 2346.35,1614 2346.35,27 22,27
  text ".Layer_Name" at 123,-1895.49 h60
Multi-Layer:
  circle w10: c519,1494 r49.5
  circle w10: c2281,1219 r49.5
  circle w10: c1878,89 r49.5

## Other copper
Top Layer:
  text ".layer_Name" at 138,-1885 h60
GND:
  text "GND" at 206,-1881 h60
PWR:
  text "PWR" at 216,-1881 h60
Bottom Layer:
  text ".Layer_Name" at 197,-1895 h60
Multi-Layer:
  pour cut-out: 1494,337 1494,308 1520,282 1997,282 1978,263 1516,263 1496,283
  pour cut-out: 464,1268 465,1269 465,1315 487,1337 1107,1337 1127,1317 1127,1348 1103,1372 484,1372 464,1352 464,1318

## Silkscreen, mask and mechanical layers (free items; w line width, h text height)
Top Overlay:
  circle w10: c2057,628 r7.28
  circle w10: c1602.66,1112 r5.66
  circle w6: c1822,754 r6
  circle w6: c2176,911 r159.53
  circle w10: c188,645.2 r7.28
  circle w10: c1895,1330 r5.39
  circle w10: c2171,1090 r8
  circle w10: c750,624 r4.12
  lines w6: 1483,776 1503,776 1513,766 1591,766 1626,731 ; 1652,705 1626,731 ; 1654,395 1714,455 1722,455 1726,455 1731,460 ; 1833.98,966.2 1855.2,966.2 1875.2,966.2 1921,1012 ; 1853,867 1875,867 1889,853 ; 1861,429 1870,420 ; 1870,448 1870,420 ; 1882,432 1870,420 ; 1626,731 1626,731 ; 1789,459 1789,593 1792,596 1925,596 1932,589 1932,462 1923,453 1795,453 1789,459 ; 1815,302 1827,290 1924,290 1934,300 1934,380 1913,401 1823,401 1815,393 1815,302
  text "TIDA-00912_E1" at 1123,54 h30
  text ".layer_Name" at 164,-1883 h60
Bottom Overlay:
  text ".Layer_Name" at 123,-1895.49 h60
Top Paste:
  text ".Layer_Name" at 111,-1898.49 h60
Bottom Paste:
  text ".Layer_Name" at 111,-1898.49 h60
Top Solder:
  text ".Layer_Name" at 139,-1906 h60
Bottom Solder:
  text ".Layer_Name" at 186,-1902 h60
Drill Guide:
  text ".layer_Name" at 194,-1899 h60
M1 Board Outline:
  the board outline again, w10
  text ".layer_Name" at 106,-1880 h60
M2 Board Dimensions:
  rectangle: 140.5,-1042 515.5,-917
  lines w6: 15.5,-792 1015.5,-792
  lines w7: 15.5,-792 15.5,-1042 1015.5,-1042 1015.5,-792 ; 140.5,-1042 140.5,-792 ; 265.5,-1042 265.5,-792 ; 515.5,-1042 515.5,-792 ; 765.5,-1042 765.5,-792
  lines w10: 15.5,-1107 15.5,-1087 ; 75.5,-1117 15.5,-1097 ; 75.5,-1077 15.5,-1097 ; 239.58,-1097 15.5,-1097 ; 791.42,-1097 1015.5,-1097 ; 955.5,-1117 1015.5,-1097 ; 955.5,-1077 1015.5,-1097 ; 1015.5,-1107 1015.5,-1087
  text "1000 (mil)" at 249.58,-1132.99 h60
  text ".layer_Name" at 136,-1873 h60
M3 3D STEP Top:
  text ".Layer_Name" at 123,-1895.49 h60
M4 3D STEP Bottom:
  text ".Layer_Name" at 123,-1895.49 h60
M5 Assembly Top:
  circle w6: c1676,1109 r5.1
  circle w10: c166,559 r12.04
  circle w10: c2053,600 r6.08
  circle w10: c604.28,875 r5.83
  circle w10: c1843,792 r3.16
  circle w6: c1863,1478 r10
  circle w10: c468,1157 r7.09
  circle w10: c2175,908 r17.46
  lines w6: 468.44,814.44 588.44,814.44 588.44,903.56 470,903.56 470,816 468.44,814.44 ; 480.44,1137.44 482,1139 482,1226.56 600.44,1226.56 600.44,1137.44 480.44,1137.44
  lines w10: -746,-1967.17 5854,-1967.17 ; -746,-1763.83 5856,-1763.83 ; -746,-1560.5 -746,-2170.5 3259,-2170.5 5856,-2170.5 5856,-1560.5 -745.5,-1560.5 -745.5,-2170.5 ; 1719,-2170.5 1719,-1560.5 ; 2986,-1763.83 2986,-1560.5 ; 3826,-1763.83 3826,-1560.5 ; 4448,-2177 4448,-1974.17
  text "COMPONENTS MARKED 'DNP' SHOULD NOT BE POPULATED." at 699.5,-1355.5 h30
  text "ASSEMBLY VARIANT:" at 699,-1471 h30
  text ".VariantName" at 1735,-1471 h30
  text "ALL ARTWORK VIEWED FROM TOP SIDE" at -682.5,-1692.67 h30
  text "BOARD #:" at 1794,-1692.67 h30
  text ".PRJ_Number" at 2339.5,-1692.67 h30
  text "REV:" at 3184,-1692.67 h30
  text ".PCB_Rev" at 3475.5,-1692.67 h30
  text "SVN REV:" at 4022,-1692.67 h30
  text ".VersionControl_RevNumber" at 4528,-1692.67 h30
  text ".layer_Name" at 81,-1875 h30
  text "LAYER NAME =" at -689,-1882 h30
  text "TID #:" at 1835,-1900.4 h30
  text ".TID" at 2016.5,-1903.4 h30
  text ".plot_File_Name" at -243,-2064 h30
  text "PLOT NAME =" at -645.5,-2072.74 h30
  text "GENERATED    :" at 1796,-2101.33 h30
  text ".Print_Date" at 2665.5,-2101.33 h30
  text ".Print_Time" at 3394.5,-2101.33 h30
  text "TEXAS INSTRUMENTS" at 4659,-2101.33 h30
M6 Assembly Bottom:
  lines w6: -746.5,-1764.33 5855.5,-1764.33 ; -744.5,-1967.67 5855.5,-1967.67 ; 1283.5,-1764.33 1283.5,-1561 ; 2123.5,-1764.33 2123.5,-1561 ; 3390.5,-2171 3390.5,-1561 ; 4279.5,-2171 5855,-2171 5855,-1561 -746.5,-1561 -746.5,-2171 1850.5,-2171 5855.5,-2171 5855.5,-1561
  text "COMPONENTS MARKED 'DNP' SHOULD NOT BE POPULATED." at 5648,-1355 h30
  text ".VariantName" at 4604,-1471 h30
  text "ASSEMBLY VARIANT:" at 5643,-1471 h30
  text "SVN REV:" at 1087.5,-1693.17 h30
  text ".PCB_Rev" at 1634,-1693.17 h30
  text "REV:" at 1925.5,-1693.17 h30
  text ".PRJ_Number" at 2770,-1693.17 h30
  text "BOARD #:" at 3315.5,-1693.17 h30
  text "PCB VIEWED FROM BOTTOM SIDE" at 5792,-1693.17 h30
  text "Not in version control" at 729,-1700 h30
  text "LAYER NAME =" at 5787,-1878 h30
  text "TID #:" at 3319.5,-1884.9 h30
  text ".Layer_Name" at 5014,-1885 h30
  text ".TID" at 3092,-1890 h30
  text "IGNORE ->" at 2093.85,-1895.49 h30
  text ".Print_Time" at 1715,-2101.83 h30
  text ".Print_Date" at 2444,-2101.83 h30
  text "GENERATED    :" at 3313.5,-2101.83 h30
  text ".plot_File_Name" at 4986.5,-2101.83 h30
  text "PLOT NAME =" at 5792,-2101.83 h30
M9 Title Sheet:
  drawing of 57 lines, arcs and shapes, not listed
  text "1" at 285.84,6999.5 h70
  text "2" at 2781.5,6999.5 h70
  text "3" at 5270.84,6999.5 h70
  text "4" at 7777.51,6999.5 h70
  text "5" at 10276.5,6999.5 h70
  text "6" at 12781.5,6999.5 h70
  text "A" at -870.5,5856.5 h70
  text "A" at 13929.5,5856.5 h70
  text "B" at -870.5,3476.5 h70
  text "B" at 13929.5,3476.5 h70
  text "C" at -870.5,1101.5 h70
  text "C" at 13929.5,1101.5 h70
  text "PROJECT TITLE:" at 10889.5,-759.5 h45
  text ".PRJ_Title" at 11391,-886 h70
  text "DESIGNED FOR:" at 10889.5,-1060.5 h45
  text ".PRJ_Customer" at 10939.5,-1200.5 h70
  text "D" at -870.5,-1268.5 h70
  text "D" at 13929.5,-1268.5 h70
  text "FILE NAME:" at 10889.5,-1360.5 h45
  text ".PCB_File_Name_No_Path" at 11221,-1486 h70
  text "Texas Instruments (TI) and/or its licensors do not warrant the accuracy or completeness of this specification" at 5920,-1642.34 h45
  text "ENGINEER:" at 10889.5,-1650.5 h45
  text "LAYOUT BY:" at 12394.5,-1650.5 h45
  text "or any information contained therein. TI and/or its licensors do not warrant that this design will meet" at 5875.02,-1755 h45
  text ".PRJ_Engineer" at 10939.5,-1805.49 h70
  text ".PCB_Layout" at 12445,-1805.49 h70
  text "the specifications, will be suitable for your application or fit for any particular purpose, or will operate in" at 5875.02,-1867.67 h45
  text ".layer_Name" at 168,-1894 h60
  text "ALTIUM DESIGNER VERSION:" at 12394.5,-1960.5 h45
  text "an implementation. TI and/or its licensors do not warrant that the design is production worthy. You should" at 5875.02,-1980.33 h45
  text "completely validate and test your design implementation to confirm the system functionality for your application." at 5920,-2093 h45
  text ".print_Scale" at 10939.5,-2093.83 h70
  text ".Application_BuildNumber" at 12445,-2093.83 h70
  text "2" at 2781.5,-2300.5 h70
  text "3" at 5270.84,-2300.5 h70
  text "4" at 7777.51,-2300.5 h70
  text "5" at 10276.5,-2300.5 h70
  text "6" at 12781.5,-2300.5 h70
M10 Fab Notes:
  drawing of 228 lines, arcs and shapes, not listed
  text "DESIGN INFORMATION" at 11927.02,5773 h60
  text "(REFER ALSO ARRAY/PANEL PROFILING INFORMATION)" at 11565.46,5611.29 h60
  text "BOARD SIZE" at 10879.46,5607 h60
  text "2371.36MIL" at 11341.78,5479.18 h60
  text "X" at 11847.46,5479.18 h60
  text "1639MIL" at 12078.78,5479.18 h60
  text "Number of Layers :" at 11282.46,5282 h60
  text "4" at 12377.27,5272 h60
  text "MIN. TRACK WIDTH:" at 11282.46,5143 h60
  text "10" at 12378.7,5143 h60
  text "MIL" at 12533.46,5143 h60
  text "MIN. CLEARANCE:" at 11282.46,5011 h60
  text "MIL" at 12533.46,5011 h60
  text "8" at 12339,5008 h60
  text "16" at 12340,4893 h60
  text "MIN. VIA DRILL SIZE:" at 11282.46,4879 h60
  text "MIL" at 12533.46,4879 h60
  text "8 MIL" at 11977.46,4737.29 h60
  text "MINIMUM ANNULAR RING" at 10953.23,4733.01 h60
  text "EXTERNAL" at 12685.46,4733.01 h60
  text "PER" at 11153.23,4615 h60
  text "IPC-D-275 CLASS 2 LEVEL C" at 11373.23,4615 h60
  text "MIL, HOLES" at 12861.46,4502.71 h60
  text "+/-" at 12469,4502 h60
  text "+/-" at 13323,4502 h60
  text "REGISTRATION TOLERANCES:" at 10953.23,4497 h60
  text "METAL" at 12153,4497 h60
  text "5" at 12729.2,4497 h60
  text "3" at 13562.2,4497 h60
  text "MIL" at 13678.46,4497 h60
  text "MATERIAL:" at 10878.46,4287.54 h60
  text "FR-4 High Tg" at 11864.9,4147.21 h60
  text "FR-408" at 11299.46,4138.64 h60
  text "X" at 11706,4139 h60
  text "OTHER" at 12787.46,4138.64 h60
  text "63 MIL (1.6mm) +/-10%" at 11619.56,3975.92 h60
  text "THICKNESS:" at 10953.23,3971.64 h60
  text "X" at 11491.4,3971.64 h60
  text "OTHER" at 12904.46,3971.64 h60
  text "TOLERANCE:" at 10953.23,3813.64 h60
  text "X" at 11792.53,3813.64 h60
  text "ANSI IPC-6012 TYPE 3 CLASS 2" at 11979.48,3813.64 h60
  text "OTHER +/-" at 11979.46,3657.64 h60
  text "BOW & TWIST:" at 10953.23,3500.64 h60
  text "X" at 11792.53,3500.64 h60
  text "ANSI IPC-6012 TYPE 3 CLASS 2" at 11979.48,3500.64 h60
  text "OTHER +/-" at 11979.46,3342.13 h60
  text "COPPER THICKNESS (FINISHED):" at 10878.46,3206.64 h60
  text "1.4MIL (1oz)" at 11758.46,3053.92 h60
  text "2MIL (1.4oz)" at 12525.46,3053.92 h60
  text "2.8MIL (2oz)" at 13252.46,3053.92 h60
  text "OUTER:" at 11235.46,3049.64 h60
  text "X" at 11630,3049 h60
  text "X" at 11630,2904 h60
  text "1.4MIL (1oz)" at 11758.46,2896.92 h60
  text "2.8MIL (2oz)" at 12525.46,2896.92 h60
  text "N/A" at 13252,2897.29 h60
  text "INNER SIGNAL:" at 10946.38,2892.64 h60
  text "DRILLING:" at 10878.46,2753.64 h60
  text "REFERENCE:" at 10953.23,2636.64 h60
  text "X" at 11601.46,2636.64 h60
  text "AS SHOWN" at 11788.46,2636.64 h60
  text "X" at 12502.46,2636.64 h60
  text "NC_DRILL FILES" at 12639.46,2636.64 h60
  text "PTH MIN COPPER THICKNESS:" at 10953.23,2478.64 h60
  text "X" at 12303.46,2478.64 h60
  text "1MIL" at 12440.46,2478.64 h60
  text "OTHER" at 12937.46,2478.64 h60
  text "BOARD FINISH:" at 10878.46,2319.64 h60
  text "SILKSCREEN:" at 11033.68,2201.64 h60
  text "X" at 11982.46,2201.64 h60
  text "TOP" at 12108.46,2201.64 h60
  text "BOTTOM" at 12619.46,2201.64 h60
  text "SILKSCREEN COLOR:" at 11033.68,2034.64 h60
  text "X" at 11981.42,2034.64 h60
  text "WHITE" at 12108.46,2034.64 h60
  text "OTHER" at 12619.46,2034.64 h60
  text "SOLDER RESIST COLOR:" at 11033.68,1864.64 h60
  text "X" at 11601.42,1705.44 h60
  text "GREEN" at 11728.46,1705.44 h60
  text "BLUE" at 12319.46,1705.44 h60
  text "OTHER" at 12857.46,1705.44 h60
  text "IMMERSION GOLD (ENIG)" at 11939.46,1516.92 h60
  text "ENEPIG" at 13277,1513.64 h60
  text "SURFACE FINISH:" at 10878.46,1512.64 h60
  text "X" at 11752.51,1512.64 h60
  text "IMM. TIN/SILVER OR EQUIV" at 11208,1355.64 h60
  text "OTHER" at 12639.46,1355.64 h60
  text "ARRAY/PANEL:" at 10878.46,1176.64 h60
  text "CUT AND TRIM PER MECH LAYER 1" at 11939.46,1172.35 h60
  text "N.C. ROUTE" at 11939.46,1020.64 h60
  text "X" at 12618.46,1020.64 h60
  text "V. SCORE" at 12805.46,1020.64 h60
  text "CERTIFICATION:" at 10878.46,883.64 h60
  text "MATERIALS AND WORKMANSHIP FOR ALL PCBS" at 11603.46,883.64 h60
  text "TO MEET OR EXCEED THE REQUIREMENTS OF:" at 11603.46,785.64 h60
  text "X" at 11229.96,649.14 h60
  text "ANSI IPC-A-600F CLASS ->" at 11368.96,649.14 h60
  text "X" at 13008.02,649.14 h60
  text "2" at 13126.96,649.14 h60
  text "1" at 12811.96,647.64 h60
  text "3" at 13480.96,647.64 h60
  text "X" at 11232.02,489.64 h60
  text "UL 94V-0" at 11368.96,489.64 h60
  text "X" at 12044.02,489.64 h60
  text "RoHS" at 12180.96,489.64 h60
  text "OTHER" at 12825.36,489.64 h60
  text "PER ORDER" at 13222.42,489.64 h60
  text "VIA TENTING:" at 12096,356 h60
  text "X" at 12863,352 h60
  text "ADDITIONAL REQUIREMENTS:" at 10878.46,348.64 h60
  text "YES" at 12645.67,346.92 h60
  text "NO" at 13010.47,341.69 h60
  text "MICROSECTION:" at 10953.23,233.64 h60
  text "YES" at 11858.96,233.64 h60
  text "IMPEDANCE CONTROL:" at 12118,227 h60
  text "YES" at 13102,226 h60
  text "X" at 13644,219 h60
  text "NO" at 13477.47,208.69 h60
  text "REQUIRED" at 12720.46,77.5 h60
  text "BARE BOARD ELEC. TEST:" at 10953.23,74.64 h60
  text "NONE" at 12258.96,74.64 h60
  text "X" at 12593.46,74.64 h60
  text "PER ORDER" at 13312.46,74.64 h60
  text "MANUFACTURER'S UL:" at 10953.23,-82.36 h60
  text "RAIL" at 12118.96,-86.65 h60
  text "METAL" at 12610.77,-86.65 h60
  text "X" at 12986,-87 h60
  text "SILK" at 13122.46,-86.65 h60
  text ".layer_Name" at 234,-1873 h60
M11 Gerber Information:
  lines w10: -746,-1967.17 5854,-1967.17 ; -746,-1763.83 5856,-1763.83 ; -746,-1560.5 -746,-2170.5 3259,-2170.5 5856,-2170.5 5856,-1560.5 -745.5,-1560.5 -745.5,-2170.5 ; 1719,-2170.5 1719,-1560.5 ; 2986,-1763.83 2986,-1560.5 ; 3826,-1763.83 3826,-1560.5 ; 4448,-2177 4448,-1974.17
  text "BOARD #:" at 1794,-1692.67 h60
  text ".PRJ_Number" at 2339.5,-1692.67 h60
  text "REV:" at 3184,-1692.67 h60
  text ".PCB_Rev" at 3475.5,-1692.67 h60
  text "SVN REV:" at 4022,-1692.67 h60
  text ".VersionControl_RevNumber" at 4528,-1692.67 h60
  text "ALL ARTWORK VIEWED FROM TOP SIDE" at -683.5,-1698.67 h60
  text "LAYER NAME =" at -685,-1882 h60
  text "TID #:" at 1824,-1906.4 h60
  text ".PRJ_Number" at 2149.5,-1907.67 h60
  text "PLOT NAME =" at -685.5,-2085.74 h60
  text ".plot_File_Name" at -8,-2088 h60
  text "GENERATED    :" at 1796,-2101.33 h60
  text ".Print_Date" at 2665.5,-2101.33 h60
  text ".Print_Time" at 3394.5,-2101.33 h60
  text "TEXAS INSTRUMENTS" at 4659,-2101.33 h60
M12 Stackup:
  lines w6: 10906,6423 13456,6423 ; 10906,6527.4 13456,6527.4 ; 10846,5938 ccw(c10880,5938) 10880,5904 13482,5904 ccw(c13482,5938) 13516,5938 13516,6644 ccw(c13482,6644) 13482,6678 10880,6678 ccw(c10880,6644) 10846,6644 10846,5938
  text "Layer Stack Up Detail for: TIDA-00912_E2" at 10906,6560.1 h57
  text "Layer" at 10906,6488.4 h24
  text "Gerber" at 11801.81,6488.4 h24
  text "Copper" at 12365.33,6488.4 h24
  text "Dielectric" at 12968.04,6488.4 h24
  text "Name" at 10906,6440.4 h24
  text "Document" at 11801.81,6440.4 h24
  text "Thickness" at 12365.33,6440.4 h24
  text "Material" at 12968.04,6440.4 h24
  text "Top Solder Mask" at 10921,6349 h34
  text "(.GTS)" at 11801.81,6347.44 h34
  text "Solder Resist" at 12968.04,6347.44 h34
  text "Top Layer" at 10916,6254 h34
  text "(.GTL)" at 11801.81,6250.69 h34
  text "1.4mil" at 12365.33,6250.69 h34
  text "FR4-High Tg" at 12997,6250 h34
  text "FR4-High Tg" at 13002,6195 h34
  text "1.4mil" at 12365.33,6185.69 h34
  text "GND" at 10915,6182 h34
  text "(.G1)" at 11800.81,6173.69 h34
  text "FR4-High Tg" at 13002,6120 h34
  text "1.4mil" at 12365.33,6115.69 h34
  text "(.G2)" at 11800.81,6103.69 h34
  text "PWR" at 10915,6102 h34
  text "FR4-High Tg" at 13002,6025 h34
  text "Bottom Layer" at 10911,6024 h34
  text "(.GBL)" at 11810,6020 h34
  text "1.4mil" at 12370,6014 h34
  text "Solder Resist" at 12962,5947 h34
  text "(.GBS)" at 11807,5940 h34
  text "Bottom Solder Mask" at 10916,5939 h34
  text ".layer_Name" at 211,-1886 h60
M13 Component Bodies Top:
  text ".Layer_Name" at 123,-1895.49 h60
M14 Component Bodies Bottom:
  text ".Layer_Name" at 123,-1895.49 h60
M15 Courtyards Top:
  text ".Layer_Name" at 123,-1895.49 h60
M16 Courtyards Bottom:
  text ".Layer_Name" at 123,-1895.49 h60
Drill Drawing:
  text ".legend" at 2948,868 h60
  text "Drill Table" at 2945,697 h60
  text "FOR 16MIL DRILL +0/-16MIL" at 2947,564 h60
  text "FOR PTH DRILL +/-3MIL" at 2947,446 h60
  text "FOR NPTH DRILL +/-2MIL" at 2940,351 h60
  text ".layer_Name" at 228,-1879 h60

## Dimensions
0,0 to 2371.36,0 on M2 Board Dimensions
0,0 to 0,1639 on M2 Board Dimensions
